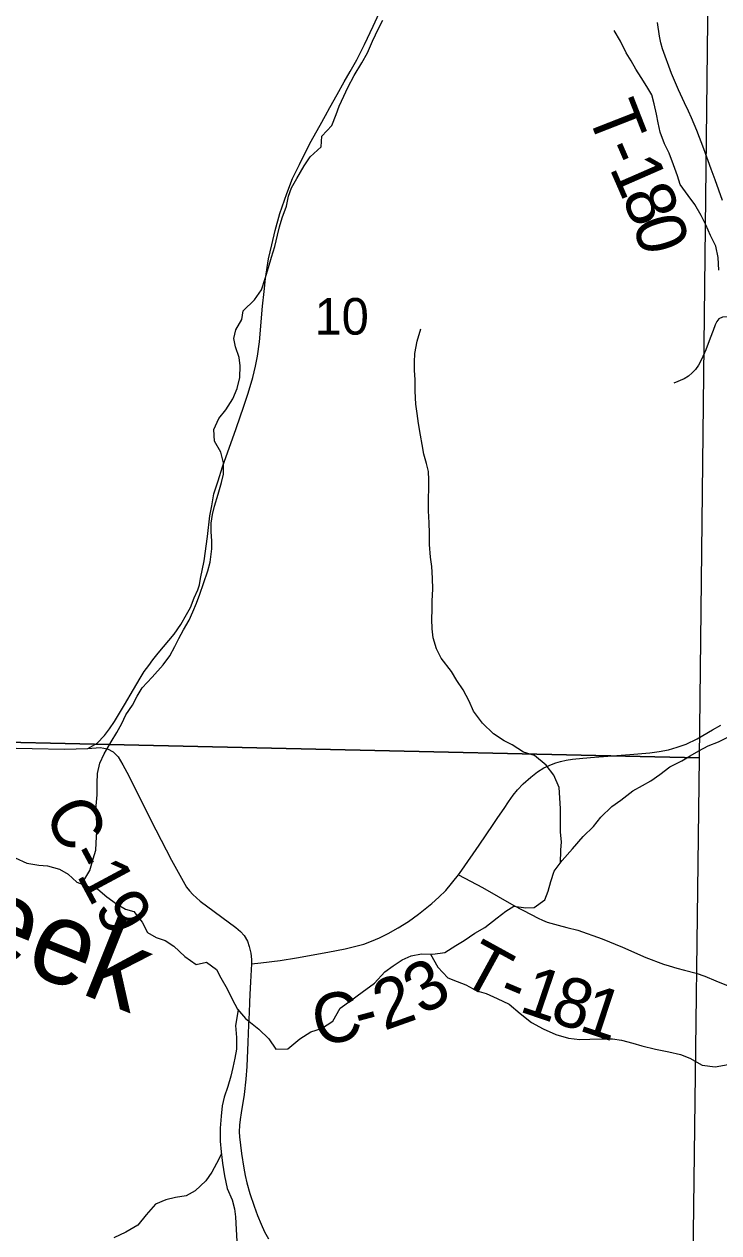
# Model space of a CAD drawing. Extents: x 0 to 34, y 0 to 22.
# Drawn here: x 25.254 to 26.05, y 17.051 to 18.434 of the extents above; entities that cross this region are included whole.
import ezdxf

# ---------------------------------------------------------------- set-up
doc = ezdxf.new("R2010")
doc.units = 0
for name, color, linetype in [('GM_X_Corporation', 7, 'Continuous'), ('GM_X_County_Road', 7, 'Continuous'), ('GM_X_County_Road_Text', 7, 'Continuous'), ('GM_X_Minor_River', 7, 'Continuous'), ('GM_X_Minor_River_Text', 7, 'Continuous'), ('GM_X_Section_Text', 7, 'Continuous'), ('GM_X_State_Route', 7, 'Continuous'), ('GM_X_Township_Road', 7, 'Continuous'), ('GM_X_Township_Road_Text', 7, 'Continuous')]:
    doc.layers.add(name, color=color, linetype=linetype)

msp = doc.modelspace()

# ---------------------------------------------------------------- linework, layer by layer
at = {"layer": 'GM_X_Corporation'}
for points in [[(25.0268, 18.6245), (26.0385, 18.6067), (26.0272, 17.5944), (25.0136, 17.617)], [(26.0272, 17.5944), (26.0142, 16.5672), (24.9957, 16.5834), (25.0136, 17.617)]]:
    msp.add_lwpolyline(points, close=True, dxfattribs=at)
at = {"layer": 'GM_X_County_Road'}
for points in [[(25.5145, 17.3584), (25.5251, 17.3597), (25.5473, 17.3625), (25.566, 17.3654), (25.6018, 17.3718), (25.6215, 17.3756), (25.643, 17.381), (25.6518, 17.3844), (25.6611, 17.3882), (25.6709, 17.3933), (25.6825, 17.3998), (25.694, 17.4071), (25.7057, 17.4155), (25.7208, 17.4277), (25.729, 17.4347), (25.737, 17.4424), (25.7514, 17.4602), (25.7551, 17.4656), (25.7753, 17.4944), (25.7913, 17.5178), (25.7967, 17.5261), (25.8037, 17.5364), (25.8086, 17.544), (25.8142, 17.5516), (25.819, 17.5575), (25.8256, 17.5646), (25.8345, 17.5723), (25.842, 17.5783), (25.8493, 17.5829), (25.858, 17.5868), (25.8628, 17.5884), (25.8683, 17.59), (25.8749, 17.5915), (25.882, 17.5928), (25.8937, 17.594), (25.9073, 17.595), (25.9329, 17.5968), (25.9479, 17.598), (25.9707, 17.5999), (25.9814, 17.6014), (25.992, 17.6035), (26.0018, 17.6064), (26.0121, 17.61), (26.0248, 17.6161), (26.0424, 17.6262), (26.052, 17.6317)], [(25.3269, 17.6049), (25.341, 17.6062), (25.3494, 17.6045), (25.356, 17.6011), (25.3615, 17.5955), (25.3668, 17.5863), (25.3716, 17.578), (25.4047, 17.5118), (25.4228, 17.4771), (25.44, 17.4464), (25.4433, 17.442), (25.4472, 17.4378), (25.4555, 17.4302), (25.4965, 17.4001), (25.5016, 17.3954), (25.5058, 17.391), (25.5097, 17.3843), (25.5118, 17.3785), (25.5136, 17.3709), (25.5144, 17.3635), (25.5145, 17.3584), (25.5132, 17.338), (25.5124, 17.3234), (25.5121, 17.3146), (25.5116, 17.3025), (25.511, 17.2886), (25.51, 17.2689), (25.5091, 17.241), (25.508, 17.2265), (25.5059, 17.2091), (25.5024, 17.1881), (25.5012, 17.1802), (25.5007, 17.1738), (25.5003, 17.1664), (25.5005, 17.1607), (25.5029, 17.1413), (25.5057, 17.1248), (25.5072, 17.1164), (25.509, 17.1077), (25.5125, 17.0958), (25.5173, 17.0811), (25.5214, 17.0703), (25.5255, 17.0605), (25.5294, 17.0518), (25.5339, 17.0436)]]:
    msp.add_lwpolyline(points, dxfattribs=at)
at = {"layer": 'GM_X_Minor_River'}
for points in [[(25.3199, 17.4499), (25.3292, 17.4654), (25.333, 17.4787), (25.336, 17.4885), (25.3367, 17.5041), (25.3374, 17.5151), (25.337, 17.5254), (25.3366, 17.5394), (25.3377, 17.5519), (25.3377, 17.5652), (25.3381, 17.5762), (25.3407, 17.588), (25.3456, 17.599), (25.3535, 17.6127), (25.36, 17.6234), (25.366, 17.6337), (25.3705, 17.6435), (25.3781, 17.6546), (25.3834, 17.6648), (25.3891, 17.6743), (25.4004, 17.6865), (25.4133, 17.7006), (25.4209, 17.7109), (25.4265, 17.7215), (25.4311, 17.731), (25.4364, 17.7406), (25.4428, 17.752), (25.4473, 17.7615), (25.4515, 17.7714), (25.4552, 17.7816), (25.4594, 17.7938), (25.4643, 17.8082), (25.4669, 17.8181), (25.4688, 17.8333), (25.4691, 17.8428), (25.468, 17.853), (25.4683, 17.8629), (25.4698, 17.8728), (25.4721, 17.8823), (25.4762, 17.896), (25.48, 17.9093), (25.4822, 17.9188), (25.4822, 17.932), (25.4791, 17.9442), (25.4719, 17.9567), (25.4711, 17.97), (25.4768, 17.9825), (25.4851, 17.9924), (25.493, 18.005), (25.498, 18.0171), (25.501, 18.0297), (25.5013, 18.043), (25.5001, 18.0525), (25.4959, 18.0646), (25.494, 18.0741), (25.4963, 18.084), (25.5031, 18.0961), (25.505, 18.106), (25.5178, 18.1186), (25.5258, 18.13), (25.5299, 18.1429), (25.5337, 18.1555), (25.5374, 18.1673), (25.5412, 18.1794), (25.5442, 18.1923), (25.5465, 18.2018), (25.5495, 18.2121), (25.5544, 18.2258), (25.5566, 18.2372), (25.56, 18.2467), (25.5661, 18.2573), (25.5748, 18.2718), (25.5816, 18.2821), (25.5941, 18.2935), (25.5948, 18.3057), (25.6065, 18.3179), (25.6114, 18.3304), (25.6148, 18.3399), (25.6201, 18.3517), (25.6246, 18.3616), (25.6318, 18.3753), (25.6409, 18.3897), (25.6473, 18.4012), (25.653, 18.4145), (25.6598, 18.4289), (25.6647, 18.4384)], [(26.0498, 18.1525), (26.049, 18.167), (26.0463, 18.1799), (26.0402, 18.192), (26.0348, 18.2041), (26.0295, 18.2148), (26.0223, 18.2276), (26.0146, 18.2379), (26.0055, 18.2504), (26.0024, 18.2602), (25.9979, 18.2728), (25.9929, 18.2864), (25.9876, 18.297), (25.9826, 18.3103), (25.9803, 18.3209), (25.9784, 18.3308), (25.9757, 18.3426), (25.973, 18.3532), (25.9673, 18.3627), (25.9608, 18.3729), (25.9547, 18.3824), (25.9494, 18.3919), (25.9437, 18.4013), (25.9372, 18.4146), (25.9296, 18.4267)], [(25.8682, 17.4737), (25.8687, 17.4887), (25.8695, 17.4982), (25.8683, 17.5092), (25.8683, 17.5362), (25.8667, 17.5605), (25.8606, 17.5745), (25.8518, 17.5858), (25.8385, 17.5968), (25.826, 17.6009), (25.8131, 17.6093), (25.8036, 17.6138), (25.7914, 17.6217), (25.7789, 17.6338), (25.7686, 17.6478), (25.7636, 17.6592), (25.7568, 17.6721), (25.7495, 17.6827), (25.7434, 17.6929), (25.7316, 17.7085), (25.7263, 17.7191), (25.7225, 17.7316), (25.7213, 17.7418), (25.7209, 17.7528), (25.7213, 17.7642), (25.7213, 17.7741), (25.722, 17.7874), (25.7216, 17.7999), (25.7208, 17.8132), (25.7192, 17.8238), (25.7181, 17.8383), (25.7184, 17.8515), (25.718, 17.8633), (25.7172, 17.877), (25.7172, 17.8906), (25.7175, 17.9028), (25.7175, 17.9123), (25.7171, 17.9218), (25.7148, 17.9313), (25.7118, 17.9419), (25.7098, 17.9529), (25.7079, 17.9635), (25.7056, 17.9768), (25.7041, 17.9882), (25.7025, 17.9992), (25.7017, 18.014), (25.7017, 18.0273), (25.7009, 18.0375), (25.7009, 18.047), (25.7016, 18.0569), (25.7043, 18.0713), (25.7084, 18.0854)], [(25.9146, 17.5264), (25.9271, 17.5386), (25.9373, 17.5459), (25.9513, 17.5565), (25.9623, 17.5627), (25.9718, 17.568), (25.982, 17.5752), (25.9934, 17.584), (26.0074, 17.5909), (26.0169, 17.5966), (26.0267, 17.6023), (26.0373, 17.6081), (26.0491, 17.6127), (26.0608, 17.6184)], [(25.2438, 17.4799), (25.2571, 17.4739), (25.2708, 17.4716), (25.2806, 17.4705), (25.2943, 17.4668), (25.3045, 17.4611), (25.3141, 17.452), (25.3266, 17.4475), (25.3384, 17.4438), (25.3486, 17.4351), (25.3596, 17.4271), (25.3699, 17.4211), (25.3794, 17.4184), (25.3893, 17.4063), (25.3954, 17.3942), (25.4053, 17.3885), (25.4155, 17.3852), (25.4254, 17.3787), (25.4379, 17.367), (25.4509, 17.3576), (25.463, 17.3603), (25.4744, 17.3519), (25.4794, 17.3425), (25.4866, 17.33), (25.4923, 17.3182), (25.4984, 17.3065), (25.5075, 17.2959), (25.5228, 17.2838), (25.5342, 17.2728), (25.5422, 17.2607), (25.5558, 17.2611), (25.5698, 17.2725), (25.5823, 17.2805), (25.5945, 17.2844), (25.6074, 17.2928), (25.616, 17.3076), (25.6282, 17.3167), (25.641, 17.3259), (25.6551, 17.3362), (25.6672, 17.3495), (25.6767, 17.3564), (25.6869, 17.3632), (25.6971, 17.3678), (25.7089, 17.3701), (25.7222, 17.3694), (25.7358, 17.3714), (25.7483, 17.3794), (25.7578, 17.3851), (25.7703, 17.3935), (25.7817, 17.4), (25.7957, 17.411), (25.8055, 17.4187), (25.815, 17.4244), (25.8287, 17.4225), (25.8382, 17.4229), (25.8503, 17.4317), (25.854, 17.4416), (25.8571, 17.4526), (25.8612, 17.4644), (25.8703, 17.4766), (25.882, 17.4903), (25.8941, 17.5044), (25.9062, 17.5158), (25.9146, 17.5264)], [(25.7192, 17.3696), (25.7279, 17.3546), (25.7393, 17.3425), (25.7499, 17.3384), (25.7598, 17.3346), (25.7723, 17.3275), (25.783, 17.3244), (25.7959, 17.3188), (25.8096, 17.3124), (25.8221, 17.3018), (25.835, 17.2912), (25.8483, 17.284), (25.8628, 17.2776), (25.8776, 17.2735), (25.8905, 17.272), (25.9019, 17.2721), (25.9151, 17.2725), (25.928, 17.2725), (25.9383, 17.271), (25.9512, 17.2677), (25.9614, 17.2647), (25.977, 17.2609), (25.9922, 17.2579), (26.0059, 17.2546), (26.0165, 17.2504), (26.0306, 17.2425), (26.0454, 17.2406), (26.0602, 17.2433)], [(25.4989, 17.3059), (25.4962, 17.2879), (25.497, 17.2742), (25.497, 17.2609), (25.4951, 17.2507), (25.4929, 17.24), (25.4906, 17.2301), (25.4872, 17.218), (25.4831, 17.2058), (25.4808, 17.1959), (25.4797, 17.1842), (25.4786, 17.1705), (25.4786, 17.1557), (25.4798, 17.1432), (25.481, 17.1303), (25.4833, 17.1159), (25.4863, 17.1014), (25.4921, 17.0886), (25.4947, 17.0783), (25.4959, 17.0688), (25.4967, 17.0544), (25.4975, 17.0411)], [(25.48, 17.141), (25.4741, 17.1299), (25.4689, 17.12), (25.462, 17.1101), (25.4499, 17.0987), (25.4397, 17.0929), (25.4272, 17.091), (25.4162, 17.0883), (25.4044, 17.0833), (25.3938, 17.0712), (25.384, 17.0594), (25.3703, 17.0513), (25.3567, 17.0449)]]:
    msp.add_lwpolyline(points, dxfattribs=at)
at = {"layer": 'GM_X_State_Route'}
msp.add_lwpolyline([(25.2266, 17.6056), (25.263, 17.6051), (25.3002, 17.6043), (25.3269, 17.6049), (25.3376, 17.6112), (25.3459, 17.6197), (25.3518, 17.6275), (25.3574, 17.636), (25.369, 17.6549), (25.3792, 17.6725), (25.3868, 17.6854), (25.3914, 17.6929), (25.3966, 17.7001), (25.4013, 17.7065), (25.4075, 17.7141), (25.4259, 17.7357), (25.4336, 17.747), (25.44, 17.7584), (25.4443, 17.7665), (25.4488, 17.7772), (25.4528, 17.7867), (25.4547, 17.7924), (25.4561, 17.7995), (25.46, 17.8196), (25.4638, 17.8474), (25.4667, 17.8713), (25.4689, 17.8827), (25.4714, 17.8964), (25.476, 17.9113), (25.4811, 17.9273), (25.4967, 17.9711), (25.5057, 17.9967), (25.5107, 18.0115), (25.5157, 18.0294), (25.5191, 18.0425), (25.5214, 18.054), (25.5237, 18.0702), (25.5269, 18.1111), (25.5287, 18.1279), (25.5303, 18.1427), (25.5339, 18.1654), (25.5375, 18.1815), (25.5415, 18.1977), (25.5469, 18.2173), (25.5549, 18.2401), (25.5615, 18.2573), (25.5692, 18.2735), (25.5813, 18.2973), (25.5932, 18.3185), (25.5993, 18.3295), (25.6041, 18.3384), (25.6125, 18.3535), (25.6205, 18.3679), (25.6273, 18.3798), (25.6349, 18.3931), (25.6439, 18.4108), (25.6536, 18.4315), (25.6606, 18.4465)], dxfattribs=at)
at = {"layer": 'GM_X_Township_Road'}
for points in [[(26.0538, 18.2323), (26.0456, 18.2559), (26.0409, 18.2681), (26.0325, 18.2913), (26.0245, 18.3121), (26.0182, 18.3268), (26.015, 18.3342), (26.0104, 18.3438), (26.0033, 18.3587), (25.9999, 18.3669), (25.9955, 18.3775), (25.9924, 18.386), (25.988, 18.3973), (25.9851, 18.4058), (25.9832, 18.4127), (25.9817, 18.4202), (25.9794, 18.436)], [(26.0931, 18.0975), (26.0863, 18.0982), (26.081, 18.0983), (26.0668, 18.099), (26.0591, 18.0991), (26.0539, 18.0984), (26.0498, 18.0967), (26.0474, 18.0938), (26.0454, 18.0898), (26.0431, 18.0832), (26.0396, 18.0745), (26.0347, 18.0613), (26.0298, 18.0502), (26.0262, 18.0437), (26.0228, 18.0387), (26.0192, 18.0349), (26.0148, 18.031), (26.0098, 18.0279), (25.9981, 18.0232)], [(25.7514, 17.4602), (25.7789, 17.446), (25.815, 17.4251), (25.8346, 17.4149), (25.8428, 17.4106), (25.8477, 17.4085), (25.853, 17.4063), (25.8655, 17.4027), (25.8754, 17.4002), (25.8881, 17.397), (25.9159, 17.3872), (25.9395, 17.3777), (25.9662, 17.3657), (25.9863, 17.3582), (25.9926, 17.3561), (26.0014, 17.3536), (26.0105, 17.3514), (26.0238, 17.3477), (26.0335, 17.3443), (26.0464, 17.3392), (26.066, 17.331)]]:
    msp.add_lwpolyline(points, dxfattribs=at)

# ---------------------------------------------------------------- texts
at = {"layer": 'GM_X_County_Road_Text'}
for s, height, rotation, p in [('C-19', 0.05682, 298.2545, (25.2754, 17.531)), ('3', 0.0568, 30.5897, (25.7101, 17.2985)), ('2', 0.0568, 19.5484, (25.6663, 17.2817)), ('C', 0.0568, 12.4183, (25.5907, 17.2635)), ('-', 0.0568, 14.9304, (25.639, 17.2742))]:
    msp.add_text(s, height=height, rotation=rotation, dxfattribs=at).set_placement(p)
at = {"layer": 'GM_X_Minor_River_Text'}
msp.add_text('Creek', height=0.0947, rotation=338.1293, dxfattribs=at).set_placement((25.0621, 17.4275))
at = {"layer": 'GM_X_Section_Text'}
msp.add_text('10', height=0.04186, rotation=0, dxfattribs=at).set_placement((25.5865, 18.0786))
at = {"layer": 'GM_X_Township_Road_Text'}
for s, rotation, p in [('T', 291.3581, (25.8982, 18.3326)), ('-', 293.4444, (25.9145, 18.291)), ('1', 293.5899, (25.9239, 18.2694)), ('8', 292.3397, (25.9378, 18.2376)), ('0', 286.2985, (25.9506, 18.2067)), ('T', 331.2438, (25.7508, 17.3385)), ('1', 341.1997, (25.8194, 17.3046)), ('-', 337.1172, (25.7938, 17.3153)), ('8', 343.199, (25.8546, 17.2927)), ('1', 341.7329, (25.8878, 17.2827))]:
    msp.add_text(s, height=0.0568, rotation=rotation, dxfattribs=at).set_placement(p)

doc.saveas('drawing.dxf')
